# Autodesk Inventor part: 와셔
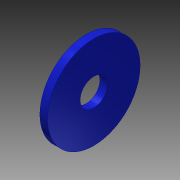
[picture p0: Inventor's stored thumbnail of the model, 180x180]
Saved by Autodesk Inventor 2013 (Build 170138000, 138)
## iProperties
Created: 2015-12
Part Number: 와셔
Material: 스테인리스강
Document SubType Name: Modeling
Designer: mduedu
Density: 8.08 g/cm^3
Mass: 6.77437 g
Surface Area: 10.3005 cm^2
Volume: 0.838413 cm^3
Author: mduedu
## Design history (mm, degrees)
sketch "스케치1"
  geometry: C1 r 2.75 at (0, 0); C2 r 11 at (0, 0); 1 further point
  constraints: 2 centre point, 2 coincident
  dimensions: "d0" = 5.5 diameter of C1; "d1" = 22 diameter of C2
extrude "돌출1" new body sketch "스케치1" stored distance "d2" = 2; taper "d3" = 0 deg
node "솔리드1"
